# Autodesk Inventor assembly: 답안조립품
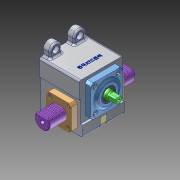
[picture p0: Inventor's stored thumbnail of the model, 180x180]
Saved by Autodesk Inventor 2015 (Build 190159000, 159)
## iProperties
Created: 2024-11
Part Number: 답안조립품
Document SubType Name: Assembly
Designer: 102-5
Author: 102-5
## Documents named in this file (10)
- C:\Users\102-5\Desktop\741104V1011\답안조립품.iam
- C:\Users\102-5\Documents\Inventor\깊음 홈 볼 베어링 6202.ipt
- C:\Users\102-5\Desktop\741104V1011\가져온 구성요소\래크\래크.ipt
- C:\Users\102-5\Desktop\741104V1011\본체.ipt
- C:\Users\102-5\Desktop\741104V1011\가져온 구성요소\수지 부시\수지 부시.ipt
- C:\Users\102-5\Desktop\741104V1011\가져온 구성요소\스톱퍼\스톱퍼.ipt
- C:\Users\102-5\Desktop\741104V1011\가져온 구성요소\오일 실 15 25 4\오일 실 15 25 4.ipt
- C:\Users\102-5\Desktop\741104V1011\가져온 구성요소\육각 소켓 머리 볼트 M4x10\육각 소켓 머리 볼트 M4x10.ipt
- C:\Users\102-5\Desktop\741104V1011\가져온 구성요소\커버\커버.ipt
- C:\Users\102-5\Desktop\741104V1011\가져온 구성요소\피니언 축\피니언 축.ipt
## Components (1 placed, 1 different names)
1. 피니언 축:1
